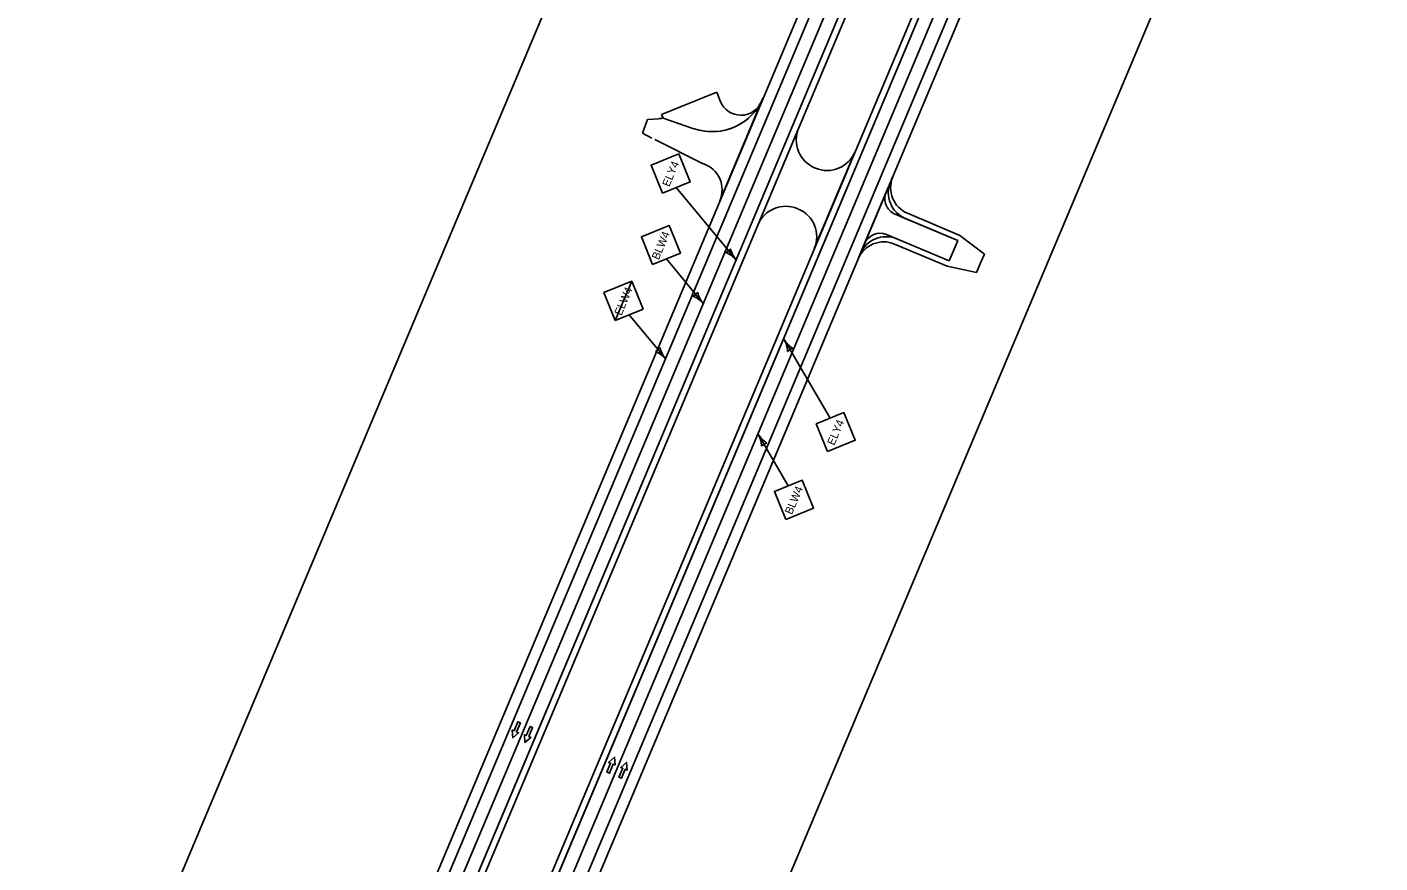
# Model space of a CAD drawing. Extents: x 14104283 to 14120882, y 8635219 to 8671666.
# Drawn here: x 14111141 to 14112358, y 8651086 to 8651838 of the extents above; entities that cross this region are included whole.
import ezdxf

# ---------------------------------------------------------------- set-up
doc = ezdxf.new("R2010")
doc.units = 0
for name, color, linetype in [('Cell', 7, 'Continuous'), ('dsnNonPlotable', 7, 'Continuous'), ('dsnPaintExistingEdgeLineRightWhite', 7, 'Continuous'), ('dsnPaintPlaceBrokenLineWhite', 7, 'Continuous'), ('dsnPaintPlaceEdgeLineLeftYellow', 7, 'Continuous'), ('dsnPaintPlaceEdgeLineRightWhite', 7, 'Continuous'), ('dsnPaintRemoveDoubleCenterLineYellow', 7, 'Continuous'), ('dsnShadingPaved', 7, 'Continuous'), ('dsnStdLabel', 7, 'Continuous'), ('dsnStgShadingPrevPav', 7, 'Continuous')]:
    doc.layers.add(name, color=color, linetype=linetype)

msp = doc.modelspace()

# ---------------------------------------------------------------- linework, layer by layer
at = {"layer": 'Cell'}
for points in [[(14111582.5, 8651212.7), (14111584.9, 8651211.7), (14111581.5, 8651203.6), (14111583.3, 8651202.9), (14111578, 8651198.3), (14111577.5, 8651205.3), (14111579.2, 8651204.6)], [(14111593.6, 8651208.5), (14111595.9, 8651207.5), (14111592.5, 8651199.4), (14111594.3, 8651198.7), (14111589, 8651194.1), (14111588.5, 8651201.1), (14111590.2, 8651200.4)], [(14111665.1, 8651166.5), (14111662.8, 8651167.4), (14111666.1, 8651175.5), (14111664.3, 8651176.2), (14111669.6, 8651180.8), (14111670.1, 8651173.9), (14111668.4, 8651174.6)], [(14111676, 8651161.9), (14111673.6, 8651162.8), (14111677, 8651170.9), (14111675.2, 8651171.6), (14111680.5, 8651176.2), (14111681, 8651169.3), (14111679.3, 8651170)]]:
    msp.add_lwpolyline(points, close=True, dxfattribs=at)
for points in [[(14111579.2, 8651204.6), (14111577.5, 8651205.3), (14111578, 8651198.3), (14111583.3, 8651202.9), (14111581.5, 8651203.6), (14111584.9, 8651211.7), (14111582.5, 8651212.7), (14111579.2, 8651204.6)], [(14111590.2, 8651200.4), (14111588.5, 8651201.1), (14111589, 8651194.1), (14111594.3, 8651198.7), (14111592.5, 8651199.4), (14111595.9, 8651207.5), (14111593.6, 8651208.5), (14111590.2, 8651200.4)], [(14111668.4, 8651174.6), (14111670.1, 8651173.9), (14111669.6, 8651180.8), (14111664.3, 8651176.2), (14111666.1, 8651175.5), (14111662.8, 8651167.4), (14111665.1, 8651166.5), (14111668.4, 8651174.6)], [(14111679.3, 8651170), (14111681, 8651169.3), (14111680.5, 8651176.2), (14111675.2, 8651171.6), (14111677, 8651170.9), (14111673.6, 8651162.8), (14111676, 8651161.9), (14111679.3, 8651170)]]:
    msp.add_lwpolyline(points, dxfattribs=at)
at = {"layer": 'dsnNonPlotable'}
msp.add_lwpolyline([(14111219.5, 8650933.3), (14111828.1, 8652377.8), (14112293.5, 8652181.8), (14111684.9, 8650737.2)], close=True, dxfattribs=at)
at = {"layer": 'dsnPaintExistingEdgeLineRightWhite'}
msp.add_line((14110924.4, 8649364.5), (14118862.5, 8668214.7), dxfattribs=at)
at = {"layer": 'dsnPaintPlaceBrokenLineWhite'}
for p, q in [((14110829.5, 8649404.5), (14118424.3, 8667439.6)), ((14110913.3, 8649369.2), (14114932.5, 8658913.4))]:
    msp.add_line(p, q, dxfattribs=at)
at = {"layer": 'dsnPaintPlaceEdgeLineLeftYellow'}
for p, q in [((14113594.8, 8655940.3), (14111420.5, 8650777)), ((14111505.3, 8650805.9), (14113533.3, 8655621.7))]:
    msp.add_line(p, q, dxfattribs=at)
at = {"layer": 'dsnPaintPlaceEdgeLineRightWhite'}
msp.add_line((14113555.5, 8655908.7), (14111402.9, 8650797.1), dxfattribs=at)
at = {"layer": 'dsnPaintRemoveDoubleCenterLineYellow'}
msp.add_line((14110913.3, 8649369.2), (14114932.5, 8658913.4), dxfattribs=at)
at = {"layer": 'dsnShadingPaved'}
for p, q in [((14113555.5, 8655612.4), (14110924.4, 8649364.5)), ((14111505.5, 8650806.3), (14113533.3, 8655621.7))]:
    msp.add_line(p, q, dxfattribs=at)
for points in [[(14118413.2, 8667444.3), (14110818.4, 8649409.2), (14109142.6, 8645431.4)], [(14109164.7, 8645422.1), (14110840.5, 8649399.8), (14118435.4, 8667434.9)]]:
    msp.add_lwpolyline(points, dxfattribs=at)
at = {"layer": 'dsnStdLabel'}
for p, q in [((14111725.2, 8651693.4), (14111779, 8651628.3)), ((14111716.4, 8651629), (14111749.4, 8651589.1)), ((14111670.3, 8651573.8), (14111685.1, 8651609)), ((14111682.8, 8651578.9), (14111715.4, 8651539.4)), ((14111822.2, 8651556.5), (14111863.6, 8651485.8)), ((14111798.9, 8651471.3), (14111826, 8651424.9))]:
    msp.add_line(p, q, dxfattribs=at)
for points in [[(14111712.7, 8651688.3), (14111737.7, 8651698.5), (14111727.5, 8651723.5), (14111702.5, 8651713.3)], [(14111703.9, 8651623.9), (14111728.9, 8651634.1), (14111718.8, 8651659.1), (14111693.8, 8651649)], [(14111670.3, 8651573.8), (14111695.3, 8651584), (14111685.1, 8651609), (14111660.1, 8651598.8)], [(14111861.3, 8651455.7), (14111886.3, 8651465.9), (14111876.1, 8651490.9), (14111851.1, 8651480.7)], [(14111823.7, 8651394.8), (14111848.7, 8651405), (14111838.5, 8651430), (14111813.5, 8651419.8)]]:
    msp.add_lwpolyline(points, close=True, dxfattribs=at)
for centre, radius, start, end in [((14111766.4, 8651642.9), 8.86, 292.8385, 328.307), ((14111761.5, 8651613.4), 22.9, 40.5727, 68.6439), ((14111796.4, 8651643.2), 22.9, 192.5015, 220.5728), ((14111736.9, 8651603.7), 8.86, 292.8385, 328.307), ((14111732, 8651574.2), 22.9, 40.5727, 68.6439), ((14111766.8, 8651604), 22.9, 192.5015, 220.5728), ((14111802.4, 8651545), 22.9, 2.1566, 30.2279), ((14111842.1, 8651568.1), 22.9, 210.2277, 238.299), ((14111702.9, 8651554), 8.86, 292.8385, 328.307), ((14111698, 8651524.4), 22.9, 40.5727, 68.6439), ((14111732.9, 8651554.3), 22.9, 192.5015, 220.5728), ((14111831.9, 8651539.9), 8.86, 102.4935, 137.962), ((14111779.1, 8651459.7), 22.9, 2.1566, 30.2279), ((14111818.8, 8651482.9), 22.9, 210.2277, 238.299), ((14111808.6, 8651454.7), 8.86, 102.4935, 137.962)]:
    msp.add_arc(centre, radius, start, end, dxfattribs=at)
at = {"layer": 'dsnStgShadingPrevPav'}
for p, q in [((14110809.2, 8649413), (14118404, 8667448.1)), ((14118413.2, 8667444.3), (14110818.4, 8649409.2)), ((14113594.8, 8655940.3), (14111420.5, 8650777)), ((14111402.9, 8650797.1), (14113555.5, 8655908.7)), ((14113533.3, 8655621.7), (14111505.5, 8650806.3)), ((14111352.5, 8650355.3), (14113564.7, 8655608.5)), ((14111712, 8651758.9), (14111761.6, 8651779)), ((14111761.6, 8651779), (14111765.1, 8651770.5)), ((14111764.4, 8651681.4), (14111803.4, 8651774.1)), ((14111699.3, 8651754.4), (14111694.9, 8651742.2)), ((14111709.6, 8651755.2), (14111699.3, 8651754.4)), ((14111713.3, 8651755.7), (14111712, 8651758.9)), ((14111741, 8651746.2), (14111713.3, 8651755.7)), ((14111741, 8651746.2), (14111713.3, 8651755.7)), ((14111694.9, 8651742.2), (14111703.2, 8651737.8)), ((14111835.2, 8651746.5), (14111798.8, 8651659.9)), ((14111705.9, 8651736.5), (14111749.5, 8651714.7)), ((14111849.4, 8651638.5), (14111885.9, 8651725.2)), ((14111850.6, 8651710.8), (14111849.6, 8651711.1)), ((14111919.9, 8651702.8), (14111918, 8651698.2)), ((14111918, 8651698.2), (14111914.1, 8651689)), ((14111914.1, 8651689), (14111894.7, 8651642.9)), ((14111834.1, 8651674.3), (14111835, 8651673.9)), ((14111978.5, 8651645.6), (14111922.1, 8651669.3)), ((14111922.1, 8651669.3), (14111931.3, 8651665.5)), ((14111980.4, 8651650.2), (14111933.3, 8651670.1)), ((14111931.3, 8651665.5), (14111978.5, 8651645.6)), ((14111894.7, 8651642.9), (14111890.8, 8651633.7)), ((14111914.3, 8651650.9), (14111970.7, 8651627.2)), ((14111923.6, 8651647), (14111914.3, 8651650.9)), ((14111921.6, 8651642.4), (14111968.8, 8651622.6)), ((14111970.7, 8651627.2), (14111923.6, 8651647)), ((14111970.7, 8651627.2), (14111978.5, 8651645.6)), ((14111978.5, 8651645.6), (14111974.6, 8651636.4)), ((14112002.4, 8651633.4), (14111980.4, 8651650.2)), ((14111890.8, 8651633.7), (14111888.9, 8651629.1)), ((14111974.6, 8651636.4), (14111970.7, 8651627.2)), ((14111999.3, 8651626), (14112002.4, 8651633.4)), ((14111968.8, 8651622.6), (14111995.4, 8651616.8)), ((14111995.4, 8651616.8), (14111999.3, 8651626))]:
    msp.add_line(p, q, dxfattribs=at)
for points in [[(14113600.3, 8655938), (14111426, 8650774.7), (14111420.5, 8650777), (14113594.8, 8655940.3)], [(14111465.6, 8650758), (14111500, 8650808.6), (14113527.8, 8655624.1), (14113533.3, 8655621.7), (14111505.5, 8650806.3), (14111503.6, 8650807.1), (14111499.8, 8650797.8), (14111471.1, 8650755.6)]]:
    msp.add_lwpolyline(points, close=True, dxfattribs=at)
for centre, radius, start, end in [((14111757.4, 8651793.5), 50, 251.0595, 337.1633), ((14111757.4, 8651793.5), 50, 251.0595, 325.2156), ((14111783.5, 8651778.3), 20, 202.0595, 337.1633), ((14111860.1, 8651736), 27, 157.1633, 247.1633), ((14111741.4, 8651691.1), 25, 337.1633, 71.0595), ((14111861, 8651735.6), 27, 247.1633, 337.1633), ((14111943, 8651693.1), 25, 157.1646, 247.1633), ((14111941, 8651688.5), 25, 157.1633, 247.1633), ((14111941, 8651688.5), 25, 157.1633, 247.1633), ((14111927.9, 8651683.2), 15, 157.1633, 247.1633), ((14111927.9, 8651683.2), 15, 157.1633, 247.1633), ((14111823.6, 8651649.4), 27, 67.1633, 157.1633), ((14111824.6, 8651649), 27, 337.1633, 67.1633), ((14111911.9, 8651619.4), 25, 67.1633, 157.1623), ((14111913.9, 8651624), 25, 67.1633, 157.1633), ((14111913.9, 8651624), 25, 67.1633, 157.1633), ((14111908.5, 8651637.1), 15, 67.1633, 157.1633), ((14111908.5, 8651637.1), 15, 67.1633, 157.1633)]:
    msp.add_arc(centre, radius, start, end, dxfattribs=at)
msp.add_open_spline([(14111712.5, 8651755.6), (14111712.4, 8651755.6), (14111712.3, 8651755.6), (14111712.2, 8651755.6), (14111712, 8651755.5), (14111711.9, 8651755.5), (14111711.8, 8651755.5), (14111711.6, 8651755.5), (14111711.5, 8651755.5), (14111711.3, 8651755.5), (14111711.2, 8651755.4), (14111711.1, 8651755.4), (14111710.9, 8651755.4), (14111710.8, 8651755.4), (14111710.6, 8651755.4), (14111710.5, 8651755.3), (14111710.4, 8651755.3), (14111710.2, 8651755.3), (14111710.1, 8651755.3), (14111709.9, 8651755.3), (14111709.8, 8651755.3), (14111709.7, 8651755.3), (14111709.6, 8651755.2)], degree=3, dxfattribs=at)

# ---------------------------------------------------------------- texts
at = {"layer": 'dsnStdLabel'}
for s, p in [('ELY4', (14111718.8, 8651693.4)), ('BLW4', (14111709.4, 8651627.7)), ('ELW4', (14111675.8, 8651577.6)), ('ELY4', (14111867.3, 8651460.8)), ('BLW4', (14111829.2, 8651398.6))]:
    msp.add_text(s, height=7.2, rotation=67.1547, dxfattribs=at).set_placement(p)

doc.saveas('drawing.dxf')
